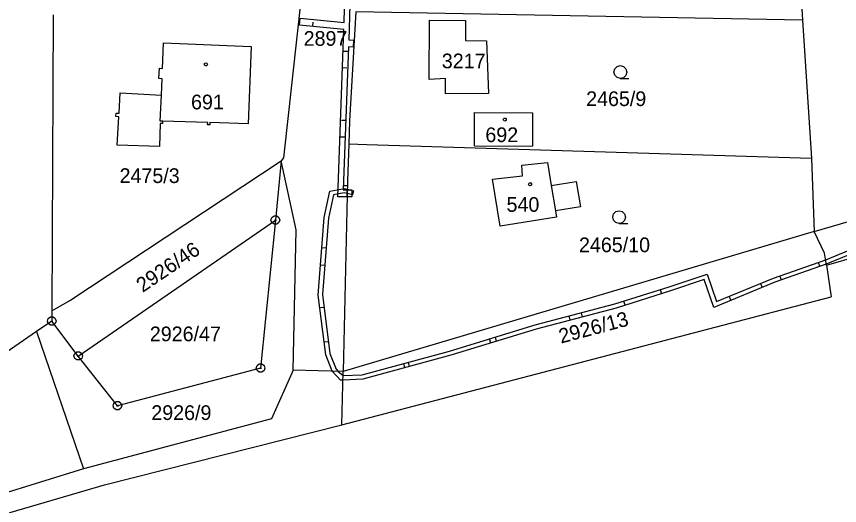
# Model space of a CAD drawing. Extents: x -760611 to -758411, y -1176479 to -1174807.
# Drawn here: x -759156.8 to -759061.6, y -1175131 to -1175074.4 of the extents above; entities that cross this region are included whole.
import ezdxf

# ---------------------------------------------------------------- set-up
doc = ezdxf.new("R2010")
doc.units = 0
for name, color, linetype in [('1', 7, 'Continuous'), ('12', 7, 'Continuous'), ('13', 7, 'Continuous'), ('2', 7, 'Continuous'), ('3', 7, 'Continuous'), ('4', 7, 'Continuous'), ('5', 7, 'Continuous'), ('8', 7, 'Continuous')]:
    doc.layers.add(name, color=color, linetype=linetype)

msp = doc.modelspace()

# ---------------------------------------------------------------- linework, layer by layer
at = {"layer": '1'}
for p, q in [((-759066.75, -1175058.1), (-759065.95, -1175074.83)), ((-759123.9, -1175072.03), (-759125.97, -1175090.74)), ((-759152.59, -1175074.2), (-759152.74, -1175108.44)), ((-759117.58, -1175073.88), (-759118.32, -1175086.48)), ((-759065.95, -1175074.83), (-759117.58, -1175073.88)), ((-759109.1, -1175081.68), (-759109.08, -1175074.83)), ((-759109.08, -1175074.83), (-759104.91, -1175074.89)), ((-759104.91, -1175074.89), (-759104.91, -1175077.2)), ((-759065.95, -1175074.83), (-759064.9, -1175090.83)), ((-759139.94, -1175080.42), (-759139.82, -1175077.46)), ((-759139.82, -1175077.46), (-759129.68, -1175077.87)), ((-759129.68, -1175077.87), (-759130.03, -1175086.81)), ((-759104.91, -1175077.2), (-759102.49, -1175077.22)), ((-759102.49, -1175077.22), (-759102.26, -1175083.32)), ((-759063.16, -1175103.17), (-758978.79, -1175078.51)), ((-759140.38, -1175081.6), (-759140.31, -1175080.4)), ((-759140.31, -1175080.4), (-759139.94, -1175080.42)), ((-759139.99, -1175081.62), (-759140.38, -1175081.6)), ((-759140.07, -1175083.49), (-759139.99, -1175081.62)), ((-759107.22, -1175081.59), (-759109.1, -1175081.68)), ((-759107.21, -1175083.36), (-759107.22, -1175081.59)), ((-759144.97, -1175085.61), (-759144.83, -1175083.22)), ((-759144.83, -1175083.22), (-759140.07, -1175083.49)), ((-759102.26, -1175083.32), (-759107.21, -1175083.36)), ((-759145.34, -1175085.99), (-759145.32, -1175085.59)), ((-759145.32, -1175085.59), (-759144.97, -1175085.61)), ((-759103.86, -1175089.35), (-759103.86, -1175085.52)), ((-759103.86, -1175085.52), (-759097.14, -1175085.54)), ((-759097.14, -1175085.54), (-759097.15, -1175089.41)), ((-759145, -1175086.01), (-759145.34, -1175085.99)), ((-759145.19, -1175089.3), (-759145, -1175086.01)), ((-759139.94, -1175086.51), (-759139.95, -1175086.79)), ((-759134.72, -1175086.67), (-759139.94, -1175086.51)), ((-759134.73, -1175086.93), (-759134.72, -1175086.67)), ((-759134.46, -1175086.68), (-759134.47, -1175086.94)), ((-759130.03, -1175086.81), (-759134.46, -1175086.68)), ((-759118.32, -1175086.48), (-759118.41, -1175089.19)), ((-759140.21, -1175086.78), (-759140.29, -1175089.45)), ((-759139.95, -1175086.79), (-759140.21, -1175086.78)), ((-759134.47, -1175086.94), (-759134.73, -1175086.93)), ((-759064.59, -1175099.26), (-759021.09, -1175086.81)), ((-759140.29, -1175089.45), (-759145.19, -1175089.3)), ((-759118.41, -1175089.19), (-759118.56, -1175093.4)), ((-759116.32, -1175089.25), (-759118.41, -1175089.19)), ((-759064.9, -1175090.83), (-759116.32, -1175089.25)), ((-759103.86, -1175089.35), (-759097.15, -1175089.41)), ((-759126.24, -1175091.09), (-759126.89, -1175097.96)), ((-759125.97, -1175090.74), (-759126.24, -1175091.09)), ((-759124.49, -1175099.08), (-759126.24, -1175091.09)), ((-759098.39, -1175091.62), (-759095.41, -1175091.31)), ((-759095.41, -1175091.31), (-759094.99, -1175093.96)), ((-759064.9, -1175090.83), (-759064.59, -1175099.26)), ((-759098.32, -1175092.83), (-759098.39, -1175091.62)), ((-759101.8, -1175093.22), (-759098.32, -1175092.83)), ((-759100.91, -1175098.66), (-759101.8, -1175093.22)), ((-759118.56, -1175093.4), (-759119.04, -1175115.49)), ((-759094.99, -1175093.96), (-759092.12, -1175093.5)), ((-759092.12, -1175093.5), (-759091.62, -1175096.43)), ((-759091.62, -1175096.43), (-759094.51, -1175096.9)), ((-759094.51, -1175096.9), (-759094.4, -1175097.61)), ((-759149.69, -1175113.68), (-759126.89, -1175097.96)), ((-759126.89, -1175097.96), (-759128.6, -1175115.08)), ((-759094.4, -1175097.61), (-759100.91, -1175098.66)), ((-759124.83, -1175115.32), (-759124.49, -1175099.08)), ((-759064.59, -1175099.26), (-759119.04, -1175115.49)), ((-759063.37, -1175101.77), (-759064.59, -1175099.26)), ((-759063.16, -1175103.17), (-759063.37, -1175101.77)), ((-759063.16, -1175103.17), (-759062.61, -1175106.85)), ((-759119.19, -1175121.65), (-759062.61, -1175106.85)), ((-759152.74, -1175108.44), (-759152.75, -1175109.64)), ((-759152.75, -1175109.64), (-759154.5, -1175110.85)), ((-759149.69, -1175113.68), (-759152.75, -1175109.64)), ((-759154.5, -1175110.85), (-759161.77, -1175115.86)), ((-759154.5, -1175110.85), (-759149.08, -1175126.73)), ((-759145.16, -1175119.44), (-759149.69, -1175113.68)), ((-759128.6, -1175115.08), (-759145.16, -1175119.44)), ((-759124.83, -1175115.32), (-759127.35, -1175120.96)), ((-759119.04, -1175115.49), (-759124.83, -1175115.32)), ((-759119.19, -1175121.65), (-759119.04, -1175115.49)), ((-759127.35, -1175120.96), (-759149.08, -1175126.73)), ((-759146.64, -1175128.58), (-759119.19, -1175121.65)), ((-759149.08, -1175126.73), (-759169.45, -1175133.02)), ((-759168.57, -1175134.99), (-759146.64, -1175128.58))]:
    msp.add_line(p, q, dxfattribs=at)
msp.add_lwpolyline([(-759152.74, -1175108.44), (-759150.67, -1175107.24), (-759126.24, -1175091.09)], dxfattribs=at)
at = {"layer": '12'}
for p, q in [((-759139.94, -1175080.42), (-759139.82, -1175077.46)), ((-759139.82, -1175077.46), (-759129.68, -1175077.87)), ((-759129.68, -1175077.87), (-759130.03, -1175086.81)), ((-759140.38, -1175081.6), (-759140.31, -1175080.4)), ((-759140.31, -1175080.4), (-759139.94, -1175080.42)), ((-759139.99, -1175081.62), (-759140.38, -1175081.6)), ((-759140.07, -1175083.49), (-759139.99, -1175081.62)), ((-759140.2, -1175086.5), (-759140.07, -1175083.49)), ((-759103.86, -1175089.35), (-759103.86, -1175085.52)), ((-759103.86, -1175085.52), (-759097.14, -1175085.54)), ((-759097.14, -1175085.54), (-759097.15, -1175089.41)), ((-759139.94, -1175086.51), (-759140.2, -1175086.5)), ((-759134.72, -1175086.67), (-759139.94, -1175086.51)), ((-759134.73, -1175086.93), (-759134.72, -1175086.67)), ((-759134.46, -1175086.68), (-759134.47, -1175086.94)), ((-759130.03, -1175086.81), (-759134.46, -1175086.68)), ((-759134.47, -1175086.94), (-759134.73, -1175086.93)), ((-759103.86, -1175089.35), (-759097.15, -1175089.41)), ((-759098.39, -1175091.62), (-759095.41, -1175091.31)), ((-759095.41, -1175091.31), (-759094.99, -1175093.96)), ((-759098.32, -1175092.83), (-759098.39, -1175091.62)), ((-759101.8, -1175093.22), (-759098.32, -1175092.83)), ((-759100.91, -1175098.66), (-759101.8, -1175093.22)), ((-759094.99, -1175093.96), (-759094.51, -1175096.9)), ((-759094.51, -1175096.9), (-759094.4, -1175097.61)), ((-759094.4, -1175097.61), (-759100.91, -1175098.66))]:
    msp.add_line(p, q, dxfattribs=at)
at = {"layer": '13'}
for p, q in [((-759122.56, -1175075.563), (-759122.511, -1175075.066)), ((-759118.469, -1175078.459), (-759118.969, -1175078.441)), ((-759119.135, -1175080.319), (-759118.635, -1175080.337)), ((-759118.755, -1175086.454), (-759119.254, -1175086.436)), ((-759119.416, -1175088.314), (-759118.916, -1175088.332)), ((-759120.58, -1175094.63), (-759118.9, -1175094.3)), ((-759118.568, -1175093.998), (-759119.068, -1175093.986)), ((-759118.9, -1175094.3), (-759118.58, -1175094.38)), ((-759121.25, -1175097.65), (-759120.58, -1175094.63)), ((-759120.16, -1175095.05), (-759120.75, -1175097.73)), ((-759118.92, -1175094.82), (-759120.16, -1175095.05)), ((-759118.59, -1175094.9), (-759118.92, -1175094.82)), ((-759118.58, -1175094.38), (-759118.59, -1175094.9)), ((-759118.59, -1175094.9), (-759118.58, -1175094.38)), ((-759121.95, -1175106.63), (-759121.25, -1175097.65)), ((-759120.75, -1175097.73), (-759121.45, -1175106.57)), ((-759063.25, -1175102.57), (-759055.6, -1175099.34)), ((-759055.42, -1175099.82), (-759063.18, -1175103.07)), ((-759121.523, -1175101.147), (-759121.024, -1175101.185)), ((-759069.3, -1175104.67), (-759063.25, -1175102.57)), ((-759064.104, -1175102.866), (-759063.94, -1175103.339)), ((-759121.184, -1175103.213), (-759121.683, -1175103.173)), ((-759063.18, -1175103.07), (-759069.12, -1175105.14)), ((-759081.34, -1175105.67), (-759076.97, -1175104.2)), ((-759076.97, -1175104.2), (-759075.87, -1175107.39)), ((-759075.87, -1175107.39), (-759069.3, -1175104.67)), ((-759068.374, -1175104.88), (-759068.538, -1175104.408)), ((-759087.63, -1175107.65), (-759081.34, -1175105.67)), ((-759077.29, -1175104.84), (-759081.18, -1175106.15)), ((-759076.17, -1175108.05), (-759077.29, -1175104.84)), ((-759069.12, -1175105.14), (-759076.17, -1175108.05)), ((-759070.788, -1175105.286), (-759070.597, -1175105.748)), ((-759121.06, -1175113.54), (-759121.95, -1175106.63)), ((-759121.45, -1175106.57), (-759120.58, -1175113.4)), ((-759081.18, -1175106.15), (-759087.49, -1175108.13)), ((-759082.384, -1175105.999), (-759082.234, -1175106.475)), ((-759086.428, -1175107.797), (-759086.578, -1175107.32)), ((-759074.204, -1175107.238), (-759074.395, -1175106.776)), ((-759121.763, -1175108.085), (-759121.267, -1175108.021)), ((-759096.86, -1175110.09), (-759087.63, -1175107.65)), ((-759087.49, -1175108.13), (-759096.73, -1175110.57)), ((-759092.808, -1175109.534), (-759092.935, -1175109.051)), ((-759091.543, -1175108.684), (-759091.415, -1175109.168)), ((-759106.75, -1175113.12), (-759096.86, -1175110.09)), ((-759096.73, -1175110.57), (-759106.61, -1175113.6)), ((-759120.755, -1175112.026), (-759121.251, -1175112.089)), ((-759101.988, -1175112.183), (-759102.135, -1175111.705)), ((-759101.491, -1175111.509), (-759101.345, -1175111.987)), ((-759116.85, -1175115.84), (-759106.75, -1175113.12)), ((-759120.31, -1175115.45), (-759121.06, -1175113.54)), ((-759120.58, -1175113.4), (-759119.87, -1175115.21)), ((-759106.61, -1175113.6), (-759116.77, -1175116.34)), ((-759119.87, -1175115.21), (-759119.62, -1175115.47)), ((-759111.92, -1175115.032), (-759112.05, -1175114.549)), ((-759111.539, -1175114.41), (-759111.409, -1175114.893)), ((-759119.36, -1175116.48), (-759120.31, -1175115.45)), ((-759119.62, -1175115.47), (-759119.05, -1175115.95)), ((-759119.05, -1175115.95), (-759116.85, -1175115.84)), ((-759119.06, -1175116.46), (-759119.36, -1175116.48)), ((-759116.77, -1175116.34), (-759119.06, -1175116.46))]:
    msp.add_line(p, q, dxfattribs=at)
for points in [[(-759118.94, -1175075.12), (-759118.28, -1175046.25), (-759117.45, -1175032.21), (-759117.8, -1175029.8)], [(-759117.87, -1175058.05), (-759118.39, -1175077.12), (-759117.86, -1175077.16), (-759117.9, -1175077.96), (-759118.45, -1175077.92), (-759119.04, -1175094.45), (-759118.58, -1175094.46), (-759118.6, -1175095.26)], [(-759118.6, -1175095.26), (-759119.66, -1175095.25), (-759118.98, -1175075.92), (-759124.1, -1175075.41), (-759124.02, -1175074.61), (-759118.94, -1175075.12)], [(-759118.58, -1175094.38), (-759117.84, -1175094.57), (-759117.96, -1175095.05), (-759118.59, -1175094.9)]]:
    msp.add_lwpolyline(points, dxfattribs=at)
msp.add_lwpolyline([(-759118.58, -1175094.46), (-759118.04, -1175094.47), (-759118.04, -1175095.27), (-759118.6, -1175095.26)], close=True, dxfattribs=at)
at = {"layer": '3'}
for points in [[(-759086.99, -1175081.57), (-759087.37, -1175081.47), (-759087.64, -1175081.2), (-759087.74, -1175080.83), (-759087.64, -1175080.46), (-759087.37, -1175080.19), (-759087, -1175080.09), (-759086.63, -1175080.19), (-759086.36, -1175080.46), (-759086.26, -1175080.84), (-759086.36, -1175081.22), (-759086.63, -1175081.49), (-759087.01, -1175081.59), (-759086.01, -1175081.59)], [(-759087.13, -1175098.35), (-759087.51, -1175098.25), (-759087.78, -1175097.98), (-759087.88, -1175097.61), (-759087.78, -1175097.24), (-759087.51, -1175096.97), (-759087.14, -1175096.87), (-759086.77, -1175096.97), (-759086.5, -1175097.24), (-759086.4, -1175097.62), (-759086.5, -1175098), (-759086.77, -1175098.27), (-759087.15, -1175098.37), (-759086.15, -1175098.37)]]:
    msp.add_lwpolyline(points, dxfattribs=at)
at = {"layer": '4'}
for p, q in [((-759140.2, -1175086.5), (-759140.07, -1175083.49)), ((-759139.94, -1175086.51), (-759140.2, -1175086.5)), ((-759094.99, -1175093.96), (-759094.51, -1175096.9))]:
    msp.add_line(p, q, dxfattribs=at)
at = {"layer": '5'}
for points in [[(-759134.93, -1175079.78), (-759134.83, -1175079.8), (-759134.78, -1175079.89), (-759134.76, -1175079.95), (-759134.78, -1175080.04), (-759134.86, -1175080.11), (-759134.93, -1175080.12), (-759135.02, -1175080.09), (-759135.08, -1175080.03), (-759135.1, -1175079.95), (-759135.08, -1175079.86), (-759135, -1175079.79)], [(-759100.36, -1175086.16), (-759100.26, -1175086.18), (-759100.21, -1175086.27), (-759100.19, -1175086.33), (-759100.21, -1175086.42), (-759100.29, -1175086.49), (-759100.36, -1175086.5), (-759100.45, -1175086.47), (-759100.51, -1175086.41), (-759100.53, -1175086.33), (-759100.51, -1175086.24), (-759100.43, -1175086.17)], [(-759097.44, -1175093.64), (-759097.34, -1175093.66), (-759097.29, -1175093.75), (-759097.27, -1175093.81), (-759097.29, -1175093.9), (-759097.37, -1175093.97), (-759097.44, -1175093.98), (-759097.53, -1175093.95), (-759097.59, -1175093.89), (-759097.61, -1175093.81), (-759097.59, -1175093.72), (-759097.51, -1175093.65)]]:
    msp.add_lwpolyline(points, close=True, dxfattribs=at)
at = {"layer": '8'}
for p, q in [((-759127.01, -1175097.96), (-759126.77, -1175097.96)), ((-759152.87, -1175109.64), (-759152.63, -1175109.64)), ((-759149.81, -1175113.68), (-759149.57, -1175113.68)), ((-759128.72, -1175115.08), (-759128.48, -1175115.08)), ((-759145.28, -1175119.44), (-759145.04, -1175119.44))]:
    msp.add_line(p, q, dxfattribs=at)
for points in [[(-759126.74, -1175097.48), (-759126.49, -1175097.66), (-759126.39, -1175097.95), (-759126.49, -1175098.24), (-759126.74, -1175098.42), (-759127.05, -1175098.42), (-759127.3, -1175098.24), (-759127.4, -1175097.95), (-759127.3, -1175097.66), (-759127.05, -1175097.48)], [(-759152.6, -1175109.16), (-759152.35, -1175109.34), (-759152.25, -1175109.63), (-759152.35, -1175109.92), (-759152.6, -1175110.1), (-759152.91, -1175110.1), (-759153.16, -1175109.92), (-759153.26, -1175109.63), (-759153.16, -1175109.34), (-759152.91, -1175109.16)], [(-759149.54, -1175113.2), (-759149.29, -1175113.38), (-759149.19, -1175113.67), (-759149.29, -1175113.96), (-759149.54, -1175114.14), (-759149.85, -1175114.14), (-759150.1, -1175113.96), (-759150.2, -1175113.67), (-759150.1, -1175113.38), (-759149.85, -1175113.2)], [(-759128.45, -1175114.6), (-759128.2, -1175114.78), (-759128.1, -1175115.07), (-759128.2, -1175115.36), (-759128.45, -1175115.54), (-759128.76, -1175115.54), (-759129.01, -1175115.36), (-759129.11, -1175115.07), (-759129.01, -1175114.78), (-759128.76, -1175114.6)], [(-759145.01, -1175118.96), (-759144.76, -1175119.14), (-759144.66, -1175119.43), (-759144.76, -1175119.72), (-759145.01, -1175119.9), (-759145.32, -1175119.9), (-759145.57, -1175119.72), (-759145.67, -1175119.43), (-759145.57, -1175119.14), (-759145.32, -1175118.96)]]:
    msp.add_lwpolyline(points, close=True, dxfattribs=at)

# ---------------------------------------------------------------- texts
at = {"layer": '2'}
for s, p in [('2897', (-759123.624, -1175077.8)), ('3217', (-759107.643, -1175080.4)), ('691', (-759136.646, -1175085.15)), ('2465/9', (-759090.953, -1175084.77)), ('692', (-759102.608, -1175088.94)), ('2475/3', (-759144.91, -1175093.67)), ('540', (-759100.158, -1175097)), ('2465/10', (-759091.781, -1175101.67)), ('2926/47', (-759141.409, -1175111.97)), ('2926/9', (-759141.24, -1175121.08))]:
    msp.add_text(s, height=1.7, dxfattribs=at).set_placement(p)
for s, rotation, p in [('2926/46', 34.20558, (-759142.241, -1175106.388)), ('2926/13', 14.9542, (-759093.859, -1175112.252))]:
    msp.add_text(s, height=1.7, rotation=rotation, dxfattribs=at).set_placement(p)

doc.saveas('drawing.dxf')
